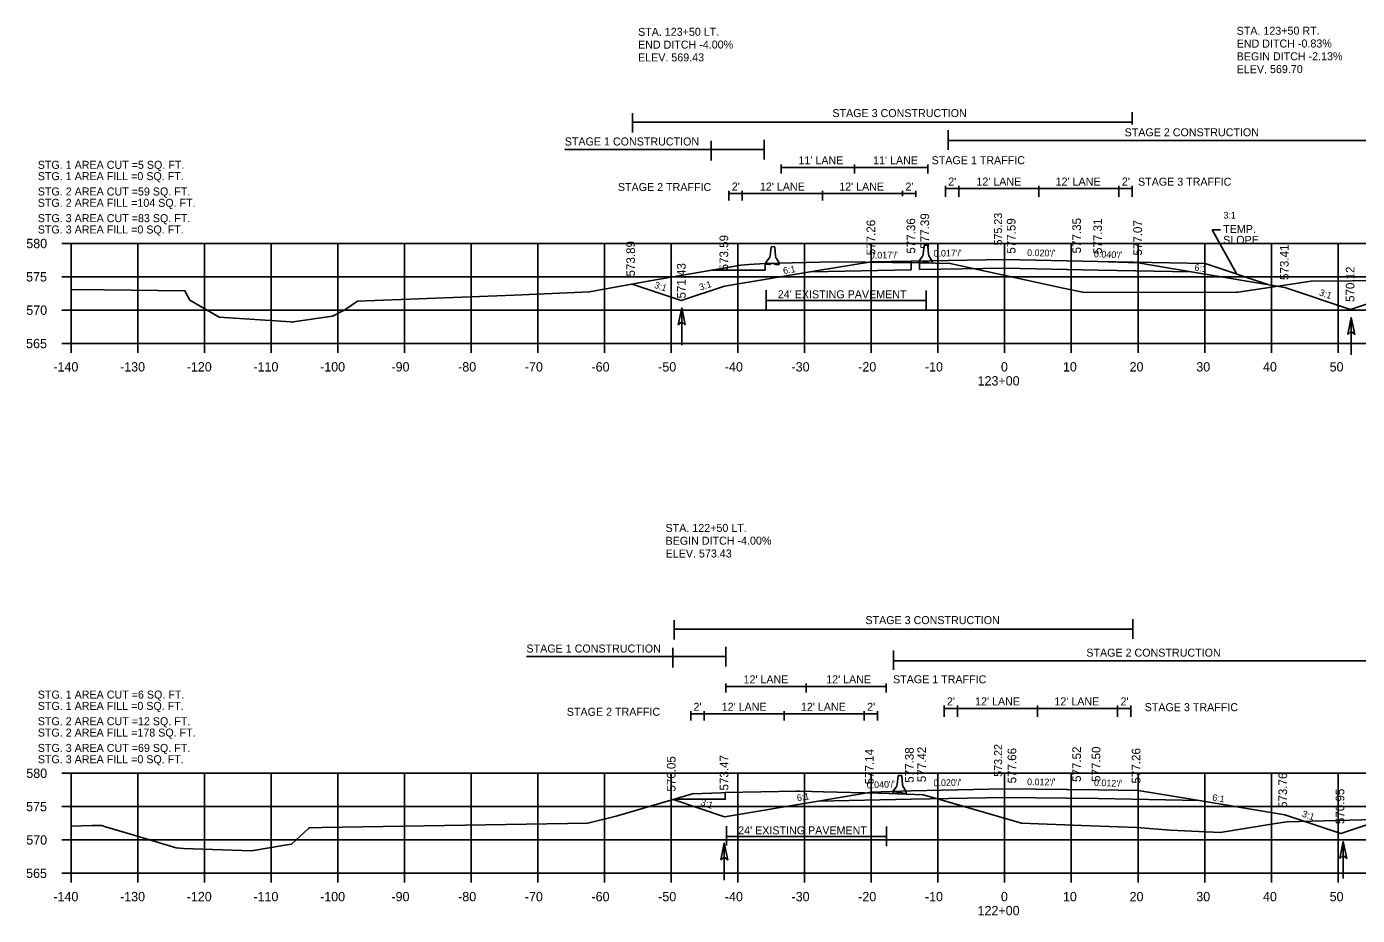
# Model space of a CAD drawing. Extents: x 642114 to 642416, y 286928 to 293347.
# Drawn here: x 642113.6 to 642313.1, y 291188.7 to 291322 of the extents above; entities that cross this region are included whole.
import ezdxf

# ---------------------------------------------------------------- set-up
doc = ezdxf.new("R2010")
doc.units = 0
for name, color, linetype in [('59', 7, 'Continuous'), ('Level 43', 7, 'Continuous'), ('Level 58', 7, 'Continuous'), ('R_Axis', 7, 'Continuous'), ('R_Axis Annot', 7, 'Continuous'), ('R_Draft', 7, 'Continuous'), ('R_Exist Surface', 7, 'Continuous'), ('R_Exist Surface Annot', 7, 'Continuous'), ('R_Fin Surface', 7, 'Continuous'), ('R_Grid', 7, 'Continuous'), ('R_MOT Barrier', 7, 'Continuous'), ('R_Xsect Elev', 7, 'Continuous'), ('R_Xsect Slope', 7, 'Continuous')]:
    doc.layers.add(name, color=color, linetype=linetype)

# ---------------------------------------------------------------- blocks, each defined once
blk = doc.blocks.new('BARRIER WALL X-SECTION')
at = {"layer": 'R_MOT Barrier'}
for p, q in [((0.8, 2.59), (0.63, 1.29)), ((0.8, 2.59), (0.87, 2.65)), ((0.87, 2.65), (1.24, 2.64)), ((1.24, 2.64), (1.31, 2.58)), ((1.31, 2.58), (1.42, 1.27)), ((0.48, 0.9), (0, 0.25)), ((0, 0.25), (0, 0)), ((0.5, -0.01), (0, 0)), ((0.5, -0.01), (1, 0.15)), ((1, 0.15), (1.5, -0.03)), ((1.56, 0.88), (2, 0.21)), ((2, 0.21), (2, -0.04)), ((1.5, -0.03), (2, -0.04))]:
    blk.add_line(p, q, dxfattribs=at)
for centre, start, end in [((-0.2, 1.39), 323.8622, 352.8452), ((2.25, 1.34), 184.8632, 213.8462)]:
    blk.add_arc(centre, 0.833, start, end, dxfattribs=at)
blk = doc.blocks.new('FA')
at = {"layer": 'Level 43'}
blk.add_lwpolyline([(7.94, 0), (0, 0)], dxfattribs=at)
at = {"layer": 'Level 58'}
blk.add_lwpolyline([(4.34, 0.75), (7.94, 0), (4.34, -0.75), (4.94, 0)], close=True, dxfattribs=at)

msp = doc.modelspace()

# ---------------------------------------------------------------- linework, layer by layer
at = {"layer": 'R_Axis'}
for p, q in [((642118.84, 291289.51), (642120.24, 291289.51)), ((642120.24, 291274.51), (642120.24, 291289.51)), ((642118.84, 291284.51), (642120.24, 291284.51)), ((642118.84, 291279.51), (642120.24, 291279.51)), ((642118.84, 291274.51), (642120.24, 291274.51)), ((642120.24, 291274.51), (642400.24, 291274.51)), ((642120.24, 291273.11), (642120.24, 291274.51)), ((642130.24, 291273.11), (642130.24, 291274.51)), ((642140.24, 291273.11), (642140.24, 291274.51)), ((642150.24, 291273.11), (642150.24, 291274.51)), ((642160.24, 291273.11), (642160.24, 291274.51)), ((642170.24, 291273.11), (642170.24, 291274.51)), ((642180.24, 291273.11), (642180.24, 291274.51)), ((642190.24, 291273.11), (642190.24, 291274.51)), ((642200.24, 291273.11), (642200.24, 291274.51)), ((642210.24, 291273.11), (642210.24, 291274.51)), ((642220.24, 291273.11), (642220.24, 291274.51)), ((642230.24, 291273.11), (642230.24, 291274.51)), ((642240.24, 291273.11), (642240.24, 291274.51)), ((642250.24, 291273.11), (642250.24, 291274.51)), ((642260.24, 291273.11), (642260.24, 291274.51)), ((642270.24, 291273.11), (642270.24, 291274.51)), ((642280.24, 291273.11), (642280.24, 291274.51)), ((642290.24, 291273.11), (642290.24, 291274.51)), ((642300.24, 291273.11), (642300.24, 291274.51)), ((642310.24, 291273.11), (642310.24, 291274.51)), ((642118.84, 291210.05), (642120.24, 291210.05)), ((642120.24, 291195.05), (642120.24, 291210.05)), ((642118.84, 291205.05), (642120.24, 291205.05)), ((642118.84, 291200.05), (642120.24, 291200.05)), ((642118.84, 291195.05), (642120.24, 291195.05)), ((642120.24, 291195.05), (642400.24, 291195.05)), ((642120.24, 291193.65), (642120.24, 291195.05)), ((642130.24, 291193.65), (642130.24, 291195.05)), ((642140.24, 291193.65), (642140.24, 291195.05)), ((642150.24, 291193.65), (642150.24, 291195.05)), ((642160.24, 291193.65), (642160.24, 291195.05)), ((642170.24, 291193.65), (642170.24, 291195.05)), ((642180.24, 291193.65), (642180.24, 291195.05)), ((642190.24, 291193.65), (642190.24, 291195.05)), ((642200.24, 291193.65), (642200.24, 291195.05)), ((642210.24, 291193.65), (642210.24, 291195.05)), ((642220.24, 291193.65), (642220.24, 291195.05)), ((642230.24, 291193.65), (642230.24, 291195.05)), ((642240.24, 291193.65), (642240.24, 291195.05)), ((642250.24, 291193.65), (642250.24, 291195.05)), ((642260.24, 291193.65), (642260.24, 291195.05)), ((642270.24, 291193.65), (642270.24, 291195.05)), ((642280.24, 291193.65), (642280.24, 291195.05)), ((642290.24, 291193.65), (642290.24, 291195.05)), ((642300.24, 291193.65), (642300.24, 291195.05)), ((642310.24, 291193.65), (642310.24, 291195.05))]:
    msp.add_line(p, q, dxfattribs=at)
at = {"layer": 'R_Exist Surface'}
for points in [[(642231.29, 291285.28), (642246.24, 291285.58)], [(642246.24, 291286.87), (642246.24, 291285.58)], [(642247.48, 291286.89), (642247.48, 291285.6)], [(642247.48, 291285.6), (642260.24, 291285.81), (642274.24, 291285.53), (642288.23, 291285.25)], [(642232.25, 291205.86), (642246.24, 291206.14), (642260.24, 291206.42), (642274.24, 291206.26), (642289.39, 291205.95)]]:
    msp.add_lwpolyline(points, dxfattribs=at)
at = {"layer": 'R_Exist Surface Annot'}
for points in [[(642120.24, 291282.59), (642125.19, 291282.58), (642137.3, 291282.42), (642138.05, 291281.03), (642142.43, 291278.46), (642153.18, 291277.74), (642153.42, 291277.73), (642153.53, 291277.75), (642159.45, 291278.63), (642161.31, 291279.54), (642163.21, 291280.87), (642186.69, 291281.74), (642198, 291282.25), (642207.05, 291283.89), (642220.7, 291286.28), (642221.88, 291286.34), (642224.34, 291286.51), (642232.53, 291286.69), (642235.48, 291286.76), (642247.39, 291286.62), (642247.54, 291286.62), (642247.6, 291286.62), (642252.07, 291286.53), (642269.03, 291282.82), (642271.94, 291282.19), (642272.46, 291282.18), (642295.06, 291282.2), (642295.27, 291282.23), (642306.22, 291283.86), (642318.47, 291283.94)], [(642120.24, 291202.1), (642123.33, 291202.2), (642124.84, 291202.23), (642125.38, 291202), (642129.49, 291200.79), (642136.01, 291198.87), (642137.09, 291198.77), (642147.31, 291198.43), (642152.31, 291199.25), (642153.31, 291199.42), (642155.83, 291201.74), (642155.98, 291201.88), (642157.86, 291201.9), (642197.71, 291202.57), (642201.96, 291203.6), (642213.41, 291206.94), (642217.69, 291207.11), (642218.35, 291207.14), (642229, 291207.35), (642229.23, 291207.35), (642229.5, 291207.35), (642233.07, 291207.26), (642241.26, 291207.07), (642241.65, 291207.05), (642248, 291206.83), (642250.19, 291206.19), (642262.76, 291202.54), (642271.75, 291202.2), (642280, 291201.89), (642285.11, 291201.52), (642292.56, 291201.17), (642300.85, 291202.51), (642302.54, 291202.77), (642323.19, 291203.32)]]:
    msp.add_lwpolyline(points, dxfattribs=at)
at = {"layer": 'R_Fin Surface'}
for points in [[(642218.24, 291283.11), (642232.25, 291285.44), (642240.24, 291286.77)], [(642246.24, 291286.87), (642240.24, 291286.77)], [(642246.24, 291286.87), (642260.24, 291287.11), (642274.24, 291286.83), (642280.24, 291286.59), (642288.23, 291285.25), (642302.24, 291282.92), (642312.11, 291279.63), (642325.45, 291284.07)], [(642204.36, 291283.4), (642211.74, 291280.94), (642218.24, 291283.11)], [(642210.52, 291206.1), (642218.24, 291203.53), (642232.25, 291205.86), (642240.24, 291207.19), (642246.24, 291207.43), (642260.24, 291207.71), (642274.24, 291207.55), (642280.24, 291207.48)], [(642280.24, 291207.48), (642288.23, 291206.15), (642302.24, 291203.81)], [(642302.24, 291203.81), (642310.67, 291201), (642317.09, 291203.14)]]:
    msp.add_lwpolyline(points, dxfattribs=at)
at = {"layer": 'R_Grid'}
for p, q in [((642120.24, 291289.51), (642400.24, 291289.51)), ((642120.24, 291274.51), (642120.24, 291289.51)), ((642130.24, 291274.51), (642130.24, 291289.51)), ((642140.24, 291274.51), (642140.24, 291289.51)), ((642150.24, 291274.51), (642150.24, 291289.51)), ((642160.24, 291274.51), (642160.24, 291289.51)), ((642170.24, 291274.51), (642170.24, 291289.51)), ((642180.24, 291274.51), (642180.24, 291289.51)), ((642190.24, 291274.51), (642190.24, 291289.51)), ((642200.24, 291274.51), (642200.24, 291289.51)), ((642210.24, 291274.51), (642210.24, 291289.51)), ((642220.24, 291274.51), (642220.24, 291289.51)), ((642230.24, 291274.51), (642230.24, 291289.51)), ((642240.24, 291274.51), (642240.24, 291289.51)), ((642250.24, 291274.51), (642250.24, 291289.51)), ((642260.24, 291274.51), (642260.24, 291289.51)), ((642270.24, 291274.51), (642270.24, 291289.51)), ((642280.24, 291274.51), (642280.24, 291289.51)), ((642290.24, 291274.51), (642290.24, 291289.51)), ((642300.24, 291274.51), (642300.24, 291289.51)), ((642310.24, 291274.51), (642310.24, 291289.51)), ((642120.24, 291284.51), (642400.24, 291284.51)), ((642120.24, 291279.51), (642400.24, 291279.51)), ((642120.24, 291274.51), (642400.24, 291274.51)), ((642120.24, 291210.05), (642400.24, 291210.05)), ((642120.24, 291195.05), (642120.24, 291210.05)), ((642130.24, 291195.05), (642130.24, 291210.05)), ((642140.24, 291195.05), (642140.24, 291210.05)), ((642150.24, 291195.05), (642150.24, 291210.05)), ((642160.24, 291195.05), (642160.24, 291210.05)), ((642170.24, 291195.05), (642170.24, 291210.05)), ((642180.24, 291195.05), (642180.24, 291210.05)), ((642190.24, 291195.05), (642190.24, 291210.05)), ((642200.24, 291195.05), (642200.24, 291210.05)), ((642210.24, 291195.05), (642210.24, 291210.05)), ((642220.24, 291195.05), (642220.24, 291210.05)), ((642230.24, 291195.05), (642230.24, 291210.05)), ((642240.24, 291195.05), (642240.24, 291210.05)), ((642250.24, 291195.05), (642250.24, 291210.05)), ((642260.24, 291195.05), (642260.24, 291210.05)), ((642270.24, 291195.05), (642270.24, 291210.05)), ((642280.24, 291195.05), (642280.24, 291210.05)), ((642290.24, 291195.05), (642290.24, 291210.05)), ((642300.24, 291195.05), (642300.24, 291210.05)), ((642310.24, 291195.05), (642310.24, 291210.05)), ((642120.24, 291205.05), (642400.24, 291205.05)), ((642120.24, 291200.05), (642400.24, 291200.05)), ((642120.24, 291195.05), (642400.24, 291195.05))]:
    msp.add_line(p, q, dxfattribs=at)
at = {"layer": 'R_Xsect Elev'}
for p, q in [((642279.36, 291307.35), (642279.36, 291309.2)), ((642204.43, 291306.14), (642204.43, 291309.06)), ((642204.43, 291307.71), (642279.36, 291307.71)), ((642251.75, 291303.58), (642251.75, 291306.51)), ((642194.27, 291303.59), (642224.19, 291303.59)), ((642216.23, 291301.98), (642216.23, 291304.91)), ((642224.19, 291302.12), (642224.19, 291305.05)), ((642251.75, 291304.97), (642325.45, 291304.97)), ((642226.7, 291300.03), (642226.7, 291301.35)), ((642237.7, 291300.03), (642237.7, 291301.35)), ((642248.7, 291300.03), (642248.7, 291301.35)), ((642226.7, 291300.93), (642248.7, 291300.93)), ((642218.9, 291295.98), (642218.9, 291297.41)), ((642220.9, 291295.98), (642220.9, 291297.41)), ((642232.9, 291295.98), (642232.9, 291297.41)), ((642244.9, 291296.6), (642244.9, 291297.41)), ((642246.9, 291296.52), (642246.9, 291297.41)), ((642251.36, 291296.5), (642251.36, 291298.16)), ((642251.36, 291297.75), (642279.36, 291297.75)), ((642253.36, 291296.5), (642253.36, 291298.16)), ((642265.36, 291296.5), (642265.36, 291298.16)), ((642277.36, 291296.5), (642277.36, 291298.16)), ((642279.36, 291296.5), (642279.36, 291298.16)), ((642218.9, 291296.99), (642246.9, 291296.99)), ((642290.33, 291286.5), (642274.24, 291286.83)), ((642290.33, 291286.5), (642299.71, 291283.38)), ((642224.47, 291279.6), (642224.47, 291282.53)), ((642248.47, 291279.51), (642248.47, 291282.44)), ((642224.47, 291280.95), (642248.47, 291280.95)), ((642210.67, 291230.09), (642210.67, 291233.02)), ((642210.67, 291231.66), (642279.47, 291231.66)), ((642279.47, 291230.23), (642279.47, 291233.16)), ((642188.53, 291227.54), (642218.45, 291227.54)), ((642210.5, 291225.93), (642210.5, 291228.86)), ((642218.45, 291226.07), (642218.45, 291229)), ((642243.55, 291225.54), (642243.55, 291228.47)), ((642243.55, 291226.92), (642317.39, 291226.92)), ((642218.45, 291222.17), (642218.45, 291223.49)), ((642230.45, 291222.17), (642230.45, 291223.49)), ((642242.45, 291222.17), (642242.45, 291223.49)), ((642218.45, 291223.07), (642242.45, 291223.07)), ((642251.17, 291218.53), (642251.17, 291220.19)), ((642251.17, 291219.78), (642279.17, 291219.78)), ((642253.17, 291218.53), (642253.17, 291220.19)), ((642265.17, 291218.53), (642265.17, 291220.19)), ((642277.17, 291218.53), (642277.17, 291220.19)), ((642279.17, 291218.53), (642279.17, 291220.19)), ((642213.16, 291217.95), (642213.16, 291219.38)), ((642213.16, 291218.97), (642241.16, 291218.97)), ((642215.16, 291217.95), (642215.16, 291219.38)), ((642227.16, 291217.95), (642227.16, 291219.38)), ((642239.16, 291217.95), (642239.16, 291219.38)), ((642241.16, 291217.95), (642241.16, 291219.38)), ((642218.52, 291199.2), (642218.52, 291202.13)), ((642242.52, 291199.11), (642242.52, 291202.04)), ((642218.52, 291200.55), (642242.52, 291200.55))]:
    msp.add_line(p, q, dxfattribs=at)
for points in [[(642291.38, 291291.56), (642295.06, 291284.93)], [(642292.6, 291291.56), (642291.38, 291291.56)], [(642216.3, 291285.51), (642224.34, 291285.51), (642224.34, 291286.51)], [(642210.67, 291206.14), (642218.35, 291206.14), (642218.35, 291207.14)]]:
    msp.add_lwpolyline(points, dxfattribs=at)

# ---------------------------------------------------------------- block references
for p in [(642247.39, 291286.62), (642224.44, 291286.39), (642243.49, 291207.07)]:
    msp.add_blockref('BARRIER WALL X-SECTION', p, dxfattribs=at)
at = {"layer": 'R_Xsect Elev', "xscale": 0.7, "yscale": 0.7}
for p, rotation in [((642211.82, 291274.28), 89.99999999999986), ((642312.23, 291272.83), 89.99999999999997), ((642218.2, 291194.01), 89.99999999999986), ((642311.02, 291194.24), 89.99999999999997)]:
    msp.add_blockref('FA', p, dxfattribs=dict(at, rotation=rotation))

# ---------------------------------------------------------------- texts
at = {"layer": '59'}
for s, p in [(' 577.39', (642248.91, 291288.24)), (' 577.35', (642271.69, 291287.54)), (' 577.26', (642240.83, 291287.26)), (' 577.36', (642246.83, 291287.5)), (' 577.59', (642261.87, 291287.5)), (' 577.31', (642274.83, 291287.45)), (' 577.07', (642280.83, 291287.21)), (' 573.89', (642204.8, 291284.08)), (' 573.59', (642218.78, 291284.99)), (' 573.41', (642302.83, 291283.55)), (' 571.43', (642212.4, 291280.77)), (' 570.12', (642312.7, 291280.26)), (' 577.14', (642240.6, 291207.9)), (' 577.38', (642246.6, 291208.14)), (' 577.42', (642248.45, 291208.23)), (' 577.66', (642261.98, 291208.05)), (' 577.52', (642271.69, 291208.26)), (' 577.50', (642274.6, 291208.26)), (' 577.26', (642280.6, 291208.02)), (' 576.05', (642210.88, 291206.81)), (' 573.47', (642218.81, 291206.98)), (' 573.76', (642302.6, 291204.35)), (' 570.95', (642311.18, 291201.94))]:
    msp.add_text(s, height=1.3, rotation=90, dxfattribs=at).set_placement(p)
at = {"layer": 'R_Axis Annot'}
for s, p in [('580', (642113.52, 291288.81)), ('575', (642113.49, 291283.81)), ('570', (642113.52, 291278.81)), ('565', (642113.49, 291273.81)), ('-140', (642117.58, 291270.31)), ('-130', (642127.58, 291270.31)), ('-120', (642137.58, 291270.31)), ('-110', (642147.58, 291270.31)), ('-100', (642157.58, 291270.31)), ('-90', (642168.28, 291270.31)), ('-80', (642178.28, 291270.31)), ('-70', (642188.28, 291270.31)), ('-60', (642198.28, 291270.31)), ('-50', (642208.28, 291270.31)), ('-40', (642218.28, 291270.31)), ('-30', (642228.28, 291270.31)), ('-20', (642238.28, 291270.31)), ('-10', (642248.28, 291270.31)), ('0', (642259.68, 291270.31)), ('10', (642268.98, 291270.31)), ('20', (642278.98, 291270.31)), ('30', (642288.98, 291270.31)), ('40', (642298.98, 291270.31)), ('50', (642308.98, 291270.31)), ('123+00', (642256.18, 291268.21)), ('580', (642113.52, 291209.35)), ('575', (642113.49, 291204.35)), ('570', (642113.52, 291199.35)), ('565', (642113.49, 291194.35)), ('-140', (642117.58, 291190.85)), ('-130', (642127.58, 291190.85)), ('-120', (642137.58, 291190.85)), ('-110', (642147.58, 291190.85)), ('-100', (642157.58, 291190.85)), ('-90', (642168.28, 291190.85)), ('-80', (642178.28, 291190.85)), ('-70', (642188.28, 291190.85)), ('-60', (642198.28, 291190.85)), ('-50', (642208.28, 291190.85)), ('-40', (642218.28, 291190.85)), ('-30', (642228.28, 291190.85)), ('-20', (642238.28, 291190.85)), ('-10', (642248.28, 291190.85)), ('0', (642259.68, 291190.85)), ('10', (642268.98, 291190.85)), ('20', (642278.98, 291190.85)), ('30', (642288.98, 291190.85)), ('40', (642298.98, 291190.85)), ('50', (642308.98, 291190.85)), ('122+00', (642256.18, 291188.75))]:
    msp.add_text(s, height=1.4, dxfattribs=at).set_placement(p)
at = {"layer": 'R_Draft'}
for s, p in [('STG. 1 AREA CUT =5 SQ. FT.', (642115.24, 291300.71)), ('STG. 1 AREA FILL =0 SQ. FT.', (642115.24, 291299.01)), ('STG. 2 AREA CUT =59 SQ. FT.', (642115.24, 291296.71)), ('STG. 2 AREA FILL =104 SQ. FT.', (642115.24, 291295.01)), ('STG. 3 AREA CUT =83 SQ. FT.', (642115.24, 291292.71)), ('STG. 3 AREA FILL =0 SQ. FT.', (642115.24, 291291.01)), ('STG. 1 AREA CUT =6 SQ. FT.', (642115.24, 291221.25)), ('STG. 1 AREA FILL =0 SQ. FT.', (642115.24, 291219.55)), ('STG. 2 AREA CUT =12 SQ. FT.', (642115.24, 291217.25)), ('STG. 2 AREA FILL =178 SQ. FT.', (642115.24, 291215.55)), ('STG. 3 AREA CUT =69 SQ. FT.', (642115.24, 291213.25)), ('STG. 3 AREA FILL =0 SQ. FT.', (642115.24, 291211.55))]:
    msp.add_text(s, height=1.2, dxfattribs=at).set_placement(p)
at = {"layer": 'R_Xsect Elev'}
for s, rotation, p in [('STA. 123+50 LT.', 0.107, (642205.26, 291320.65)), ('STA. 123+50 RT.', 0.107, (642295.03, 291320.81)), ('END DITCH -4.00%', 0.107, (642205.26, 291318.73)), ('END DITCH -0.83%', 0.107, (642295.04, 291318.89)), ('ELEV. 569.43', 0.107, (642205.26, 291316.81)), ('BEGIN DITCH -2.13%', 0.107, (642295.04, 291316.97)), ('ELEV. 569.70', 0.107, (642295.04, 291315.05)), ('575.23', 90, (642259.85, 291289.21)), ('STA. 122+50 LT.', 0.107, (642209.39, 291246.24)), ('BEGIN DITCH -4.00%', 0.107, (642209.39, 291244.32)), ('ELEV. 573.43', 0.107, (642209.4, 291242.4)), ('573.22', 90, (642259.86, 291209.52))]:
    msp.add_text(s, height=1.2, rotation=rotation, dxfattribs=at).set_placement(p)
for s, p in [('STAGE 3 CONSTRUCTION', (642234.41, 291308.47)), ('STAGE 1 CONSTRUCTION', (642194.27, 291304.21)), ('STAGE 2 CONSTRUCTION', (642278.23, 291305.59)), ("11' LANE", (642229.32, 291301.39)), ("11' LANE", (642240.51, 291301.39)), ('STAGE 1 TRAFFIC', (642249.29, 291301.4)), ("2'", (642251.78, 291298.2)), ("12' LANE", (642256, 291298.2)), ("12' LANE", (642267.89, 291298.2)), ("2'", (642277.82, 291298.2)), ('STAGE 3 TRAFFIC', (642280.24, 291298.18)), ('STAGE 2 TRAFFIC', (642202.24, 291297.38)), ("2'", (642219.32, 291297.45)), ("12' LANE", (642223.54, 291297.45)), ("12' LANE", (642235.43, 291297.45)), ("2'", (642245.36, 291297.45)), ('TEMP.', (642293.01, 291291.08)), ('SLOPE', (642293.01, 291289.45)), ("24' EXISTING PAVEMENT", (642226.22, 291281.29)), ('STAGE 3 CONSTRUCTION', (642239.36, 291232.42)), ('STAGE 1 CONSTRUCTION', (642188.53, 291228.16)), ('STAGE 2 CONSTRUCTION', (642272.49, 291227.54)), ("12' LANE", (642221.08, 291223.53)), ("12' LANE", (642233.48, 291223.53)), ('STAGE 1 TRAFFIC', (642243.5, 291223.54)), ("2'", (642251.59, 291220.23)), ("12' LANE", (642255.81, 291220.23)), ("12' LANE", (642267.7, 291220.23)), ("2'", (642277.62, 291220.23)), ('STAGE 2 TRAFFIC', (642194.58, 291218.67)), ("2'", (642213.58, 291219.42)), ("12' LANE", (642217.81, 291219.42)), ("12' LANE", (642229.69, 291219.42)), ("2'", (642239.62, 291219.42)), ('STAGE 3 TRAFFIC', (642281.24, 291219.36)), ("24' EXISTING PAVEMENT", (642220.28, 291200.89))]:
    msp.add_text(s, height=1.2, dxfattribs=at).set_placement(p)
at = {"layer": 'R_Xsect Slope'}
for s, rotation, p in [('3:1', 0.32, (642293.06, 291293.25)), ("0.017'/'", 0.9517, (642240.03, 291287.24)), ("0.017'/'", 0.9517, (642249.58, 291287.53)), ("0.020'/'", 358.8542, (642263.6, 291287.64)), ("0.040'/'", 357.7094, (642273.62, 291287.45)), ('6:1', 9.4642, (642227.09, 291284.92)), ('6:1', 350.5358, (642288.65, 291285.47)), ('3:1', 341.5668, (642207.61, 291282.89)), ('3:1', 18.4332, (642214.62, 291282.43)), ('3:1', 341.5668, (642307.33, 291281.75)), ("0.040'/'", 2.2906, (642239.57, 291207.77)), ("0.020'/'", 1.1458, (642249.58, 291208.1)), ("0.012'/'", 359.329, (642263.6, 291208.27)), ("0.012'/'", 357.7094, (642273.62, 291208.17)), ('3:1', 341.5668, (642214.54, 291205.29)), ('6:1', 9.4642, (642229.16, 291205.85)), ('6:1', 350.5358, (642291.32, 291205.97)), ('3:1', 341.5668, (642304.75, 291203.56))]:
    msp.add_text(s, height=1, rotation=rotation, dxfattribs=at).set_placement(p)

doc.saveas('drawing.dxf')
